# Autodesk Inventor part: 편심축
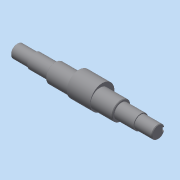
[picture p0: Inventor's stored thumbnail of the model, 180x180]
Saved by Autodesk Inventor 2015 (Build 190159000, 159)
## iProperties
Created: 2015-10
Part Number: 편심축
Document SubType Name: Modeling
Designer: mdu
Density: 1 g/cm^3
Material: 일반
Mass: 168.947 g
Surface Area: 248.524 cm^2
Volume: 168.947 cm^3
Appearance: 기본값
Author: mdu
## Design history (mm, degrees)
sketch "스케치1"
  geometry: L1 (-20.5, -41.331)-(-20.5, 32.669) reference; L2 (7.5, -30.031)-(7.5, 21.369) reference; L3 (135.5, -30.331)-(135.5, 21.669) reference; L4 (121.5, 21.369)-(121.5, -30.031) reference; L5 (184.5, -4.331)-(-57.5, -4.331); L6 (184.5, -4.331)-(184.5, 6.669); L7 (154.5, 8.169)-(121.5, 8.169); L8 (121.5, 8.169)-(121.5, 11.669); L9 (121.5, 11.669)-(7.5, 11.669); L10 (7.5, 11.669)-(7.5, 8.169); L11 (7.5, 8.169)-(-27.5, 8.169); L12 (-27.5, 8.169)-(-27.5, 6.669); L13 (-27.5, 6.669)-(-57.5, 6.669); L14 (-57.5, 6.669)-(-57.5, -4.331); L15 (154.5, 8.169)-(154.5, 6.669); L16 (154.5, 6.669)-(184.5, 6.669); C1 r 32.5 at (64.5, -4.331) reference; 1 further point
  constraints: 24 end point, 8 perpendicular, 5 point on line, 3 parallel, 2 collinear
  dimensions: "d1" = 25 diameter of L11 L5; "d2" = 32 diameter of L9 L5; "d3" = 22 diameter of L13 L5; "d4" = 35 distance of L10.end L11.end; "d5" = 30 distance of L12.end L13.end; "d15" = 33 distance of L7.start L7.end; "d26" = 30 distance of L15.end L6.end
revolve "회전1" sketch "스케치1" stored, may be unused: angle "d6" = 90 deg
node "작업 평면1"
sketch "스케치2"
  geometry: C1 r 16 at (0, 0) reference; C2 r 16 at (0, 0) reference; C3 r 20.75 at (0, 4); C4 r 16 at (0, 0) reference; 1 further point
  constraints: 1 centre point, 1 vertical alignment
  dimensions: "d8" = 41.5 diameter of C3; "d25" = 4 distance of C3.centre C1.centre
extrude "돌출1" join sketch "스케치2" stored distance "d9" = 40; taper "d10" = 0 deg
chamfer "모따기1" distance "d11" = 1; stored, may be unused: second distance "d12" = 2, angle "d13" = 45 deg
node "작업 평면2"
sketch "스케치3"
  geometry: L1 (-15, -10)-(-15, 10) reference; L2 (-15, 3)-(0, 3); L3 (0, -3)-(-15, -3); A1 r 3 centre (0, 0) between (0, -3) and (0, 3); 2 further points
  constraints: 4 end point, 2 perpendicular, 2 point on circle, 2 point on line, 2 tangent, 1 centre point, 1 horizontal alignment, 1 midpoint
  dimensions: "d16" = 18 dimension on A1 L1; "d17" = 6 distance between parallel lines of L3 L2
extrude "돌출2" cut sketch "스케치3" distance "d18" = 3.5; taper "d19" = 0 deg
node "작업 평면3"
sketch "스케치5"
  geometry: C1 r 20.75 at (0, 0) reference; 1 further point
feature "돌출 곡면1" sketch "스케치5" dims "d27" = 40, "d28" = 0
node "솔리드1"
mirror "대칭1"
node "참조1"
node "참조2"
node "참조3"
node "참조4"
node "참조5"
node "투영된 루프1"
node "곡면1"
